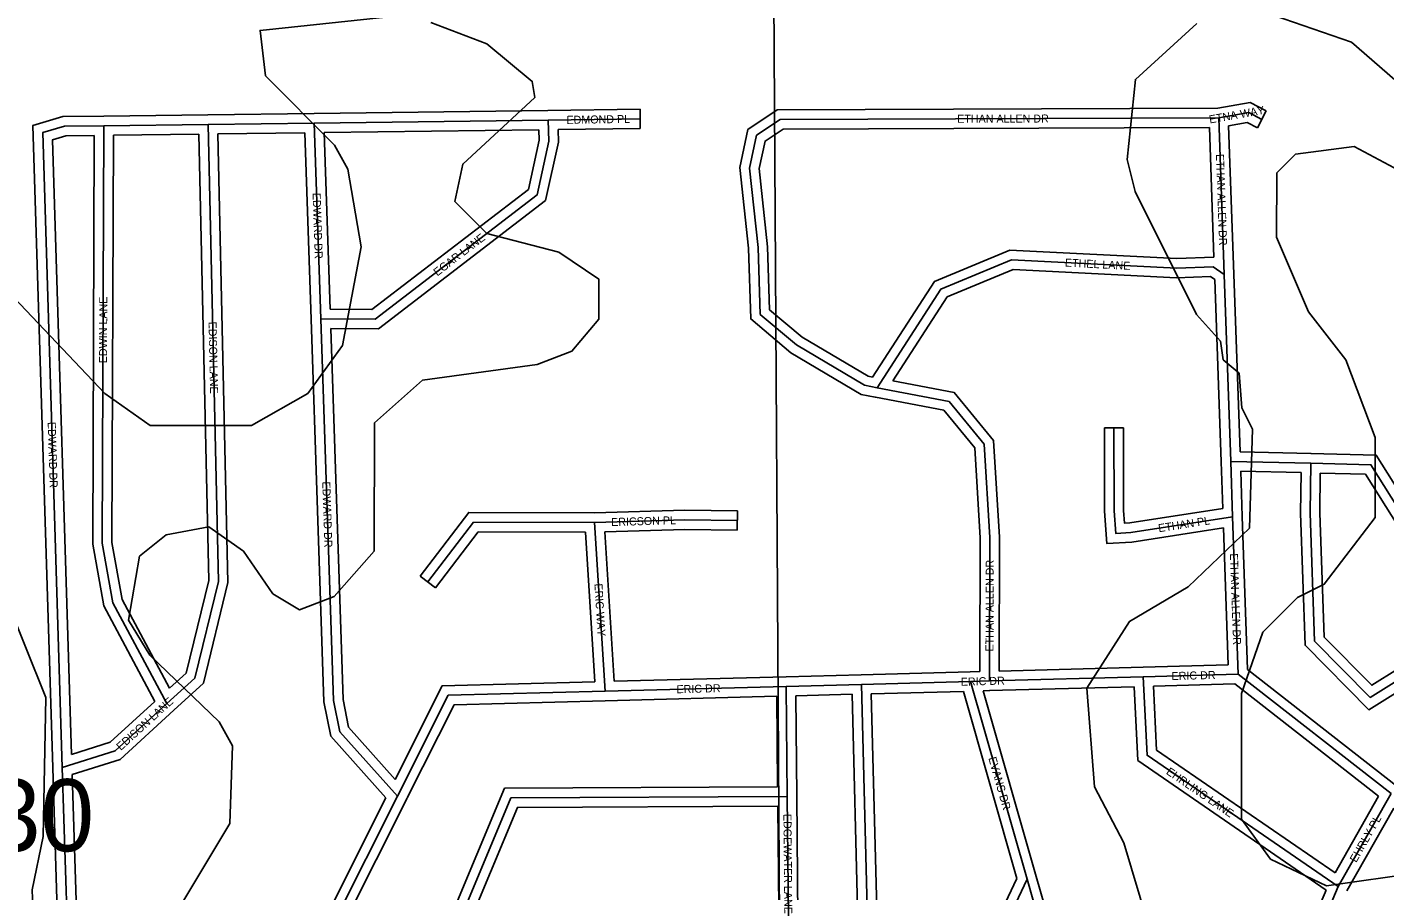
# Model space of a CAD drawing. Extents: x 457167 to 656239, y 1787309 to 1969297.
# Drawn here: x 577714 to 581955, y 1873995 to 1876691 of the extents above; entities that cross this region are included whole.
import ezdxf

# ---------------------------------------------------------------- set-up
doc = ezdxf.new("R2010")
doc.units = 0
for name, color, linetype in [('Level 1', 7, 'Continuous'), ('Level 2', 7, 'Continuous'), ('Level 31', 7, 'Continuous'), ('Level 32', 7, 'Continuous'), ('Level 34', 7, 'Continuous'), ('Level 7', 7, 'Continuous')]:
    doc.layers.add(name, color=color, linetype=linetype)

msp = doc.modelspace()

# ---------------------------------------------------------------- linework, layer by layer
at = {"layer": 'Level 1'}
msp.add_line((580044.647, 1877084.268), (580077.699, 1871707.169), dxfattribs=at)
at = {"layer": 'Level 31'}
for p, q in [((578279.362, 1876387.711), (577953.895, 1876383.669)), ((578610.875, 1876391.743), (578279.362, 1876387.711)), ((579341.346, 1876401.132), (578610.875, 1876391.743)), ((578610.875, 1876391.743), (578631.551, 1875781.157)), ((579628.955, 1876405.265), (579341.346, 1876401.132)), ((581436.002, 1876408.124), (581453.153, 1875919.365)), ((581453.153, 1875919.365), (581473.614, 1875335.691)), ((581473.614, 1875335.691), (581479.628, 1875162.589)), ((581473.614, 1875335.691), (581723.668, 1875329.733)), ((581722.084, 1875174.465), (581723.668, 1875329.733)), ((581479.628, 1875162.589), (581496.775, 1874670.921)), ((579519.327, 1874618.228), (579486.689, 1875144.474)), ((580660.933, 1874648.249), (580320.169, 1874639.126)), ((580719.795, 1874649.948), (580660.933, 1874648.249)), ((580660.933, 1874648.249), (580837.53, 1874030.803)), ((581200.555, 1874662.791), (580719.795, 1874649.948)), ((581496.775, 1874670.921), (581200.555, 1874662.791)), ((581496.775, 1874670.921), (581974.538, 1874298.328)), ((580085.357, 1874633.062), (579519.327, 1874618.228)), ((580320.169, 1874639.126), (580085.357, 1874633.062)), ((580085.357, 1874633.062), (580088.472, 1874289.786)), ((580320.169, 1874639.126), (580341.096, 1873824.907)), ((577824.003, 1874379.953), (577882.081, 1872499.116)), ((578870.615, 1874289.976), (578496.12, 1873546.181)), ((580088.472, 1874289.786), (580091.83, 1873909.781)), ((581974.538, 1874298.328), (581809.469, 1874008.115)), ((580837.53, 1874030.803), (580057.86, 1872392.042)), ((580837.53, 1874030.803), (580932.308, 1873699.341)), ((581809.469, 1874008.115), (581764.395, 1873902.388))]:
    msp.add_line(p, q, dxfattribs=at)
for points in [[(577953.895, 1876383.669), (577830.454, 1876382.111), (577762.965, 1876362.255), (577824.003, 1874379.953)], [(577953.895, 1876383.669), (577948.923, 1875080.05), (577982.256, 1874894.163), (578150.35, 1874579.171)], [(578279.362, 1876387.711), (578311.368, 1874960.742), (578237.876, 1874658.716), (578150.35, 1874579.171)], [(578631.551, 1875781.157), (578801.12, 1875779.349), (579306.822, 1876167.751), (579343.755, 1876335.309), (579341.346, 1876401.132)], [(581436.002, 1876408.124), (580066.077, 1876403.273), (579992.167, 1876353.971), (579970.641, 1876251.471), (579997.175, 1876003.781), (580003.746, 1875794.677), (580117.129, 1875699.173), (580330.03, 1875573.283), (580369.146, 1875565.566)], [(581436.002, 1876408.124), (581529.887, 1876424.662), (581570.885, 1876403.489)], [(580369.146, 1875565.566), (580567.98, 1875873.523), (580788.958, 1875965.072), (581304.937, 1875938.573), (581419.159, 1875943.069), (581453.153, 1875919.365)], [(578631.551, 1875781.157), (578671.06, 1874588.718), (578690.583, 1874491.587), (578870.615, 1874289.976)], [(580369.146, 1875565.566), (580593.673, 1875522.927), (580703.48, 1875389.25), (580721.023, 1875097.943), (580719.795, 1874649.948)], [(581479.628, 1875162.589), (581161.377, 1875113.413), (581114.286, 1875110.963), (581109.02, 1875181.519), (581108.906, 1875440.426)], [(581723.668, 1875329.733), (581911.367, 1875325.356), (582147.958, 1874948.886), (582179.237, 1874839.37), (582187.374, 1874771.718), (581909.596, 1874598.456), (581735.599, 1874774.076), (581722.084, 1875174.465)], [(579486.689, 1875144.474), (579768.27, 1875152.984), (579932.433, 1875151.191)], [(578965.489, 1874959.375), (579108.408, 1875145.986), (579486.689, 1875144.474)], [(581200.555, 1874662.791), (581212.47, 1874418.041), (581809.469, 1874008.115)], [(579519.327, 1874618.228), (579029.338, 1874605.426), (578870.615, 1874289.976)], [(578150.35, 1874579.171), (577988.92, 1874431.969), (577824.003, 1874379.953)], [(580088.472, 1874289.786), (579225.296, 1874285.021), (578788.511, 1873238.663)]]:
    msp.add_lwpolyline(points, dxfattribs=at)
at = {"layer": 'Level 32'}
for p, q in [((579340.961, 1876431.13), (578610.489, 1876421.741)), ((579628.524, 1876435.261), (579340.915, 1876431.129)), ((579629.386, 1876375.266), (579628.524, 1876435.261)), ((581584.651, 1876430.144), (581557.118, 1876376.833)), ((578278.99, 1876417.71), (577953.523, 1876413.667)), ((578610.51, 1876421.741), (578278.998, 1876417.71)), ((581466.9, 1876383.104), (581483.135, 1875920.416)), ((578250.036, 1876357.343), (577983.783, 1876354.036)), ((578581.885, 1876361.387), (578310.035, 1876358.081)), ((578581.885, 1876361.387), (578601.569, 1875780.141)), ((579312.439, 1876370.756), (578641.895, 1876362.138)), ((578641.895, 1876362.139), (578660.565, 1875810.85)), ((579629.386, 1876375.266), (579372.45, 1876371.575)), ((581407.041, 1876378.02), (581421.247, 1875973.176)), ((581483.135, 1875920.415), (581502.605, 1875365.008)), ((581423.698, 1875903.331), (581443.632, 1875334.64)), ((581078.906, 1875440.412), (581138.907, 1875440.44)), ((581502.605, 1875365.008), (581724.383, 1875359.725)), ((581443.631, 1875334.649), (581448.722, 1875188.169)), ((581504.701, 1875304.94), (581509.611, 1875163.63)), ((581504.701, 1875304.94), (581693.368, 1875300.446)), ((581692.079, 1875174.111), (581693.368, 1875300.446)), ((581752.091, 1875174.818), (581753.358, 1875299.031)), ((579932.76, 1875181.191), (579932.105, 1875121.193)), ((581509.611, 1875163.634), (581526.27, 1874685.963)), ((579487.46, 1874647.405), (579458.485, 1875114.586)), ((579547.479, 1874648.976), (579518.55, 1875115.422)), ((581450.824, 1875127.781), (581465.74, 1874700.08)), ((578941.67, 1874977.616), (578989.306, 1874941.134)), ((581199.754, 1874692.781), (580749.881, 1874680.762)), ((581465.74, 1874700.08), (581199.732, 1874692.781)), ((580084.572, 1874663.051), (579547.479, 1874648.976)), ((580319.395, 1874669.117), (580084.583, 1874663.052)), ((580660.13, 1874678.239), (580319.366, 1874669.116)), ((580689.875, 1874679.097), (580660.067, 1874678.237)), ((581526.27, 1874685.962), (581992.988, 1874321.985)), ((580055.635, 1874602.271), (579520.113, 1874588.237)), ((580055.635, 1874602.271), (580058.2, 1874319.618)), ((580290.95, 1874608.361), (580115.625, 1874603.831)), ((580115.625, 1874603.832), (580118.471, 1874290.057)), ((580290.95, 1874608.361), (580311.105, 1873824.136)), ((580638.486, 1874617.636), (580350.93, 1874609.938)), ((580350.93, 1874609.938), (580370.31, 1873855.923)), ((580638.485, 1874617.636), (580805.569, 1874033.453)), ((580720.661, 1874619.959), (580700.395, 1874619.374)), ((580700.395, 1874619.375), (580866.375, 1874039.053)), ((581172.019, 1874632.016), (580720.597, 1874619.957)), ((581486.825, 1874640.635), (581232.011, 1874633.642)), ((581486.825, 1874640.635), (581935.64, 1874290.619)), ((577794.018, 1874379.027), (577852.096, 1872498.19)), ((577854.691, 1874358.174), (577911.165, 1872529.265)), ((578834.635, 1874285.227), (578466.44, 1873553.941)), ((578901.508, 1874284.621), (578532.414, 1873551.55)), ((580118.471, 1874290.05), (580121.83, 1873910.046)), ((581935.64, 1874290.618), (581799.535, 1874051.327)), ((580058.737, 1874259.62), (580061.57, 1873939.104)), ((581983.447, 1874253.309), (581836.395, 1873994.772)), ((580805.569, 1874033.453), (580046.973, 1872438.987)), ((580866.375, 1874039.051), (580961.152, 1873707.587)), ((581772.24, 1873997.286), (581736.798, 1873914.153))]:
    msp.add_line(p, q, dxfattribs=at)
for points in [[(581433.328, 1876438.114), (580056.94, 1876433.241), (579965.325, 1876372.129), (579940.305, 1876252.993), (579967.225, 1876001.71), (579974.18, 1875780.356), (580099.71, 1875674.621), (580319.183, 1875544.845), (580363.34, 1875536.134)], [(581433.328, 1876438.114), (581534.656, 1876455.964), (581584.651, 1876430.144)], [(577953.516, 1876413.667), (577825.946, 1876412.058), (577732.265, 1876384.494), (577794.017, 1874379.03)], [(581466.9, 1876383.103), (581525.119, 1876393.36), (581557.118, 1876376.833)], [(577923.779, 1876353.285), (577834.96, 1876352.166), (577793.665, 1876340.015), (577852.77, 1874420.483)], [(577923.78, 1876353.285), (577918.913, 1875077.438), (577953.561, 1874884.211), (578112.903, 1874585.621)], [(577983.783, 1876354.037), (577978.934, 1875082.661), (578010.95, 1874904.114), (578158.68, 1874627.282)], [(578250.036, 1876357.344), (578281.286, 1874964.008), (578210.9, 1874674.738), (578158.68, 1874627.282)], [(578310.035, 1876358.081), (578341.449, 1874957.476), (578264.854, 1874642.695), (578172.625, 1874558.876)], [(578660.565, 1875810.849), (578791.07, 1875809.459), (579279.878, 1876184.884), (579313.635, 1876338.033), (579312.439, 1876370.756)], [(578662.575, 1875750.824), (578811.17, 1875749.24), (579333.766, 1876150.616), (579373.875, 1876332.585), (579372.449, 1876371.576)], [(581407.04, 1876378.02), (580075.213, 1876373.306), (580019.008, 1876335.814), (580000.976, 1876249.948), (580027.125, 1876005.853), (580033.311, 1875808.998), (580134.547, 1875723.726), (580340.878, 1875601.722), (580354.985, 1875598.939)], [(580354.985, 1875598.939), (580547.852, 1875897.657), (580783.733, 1875995.381), (581305.116, 1875968.603), (581421.247, 1875973.176)], [(580418.52, 1875586.726), (580588.108, 1875849.389), (580794.184, 1875934.763), (581304.757, 1875908.542), (581410.268, 1875912.696), (581423.697, 1875903.331)], [(578601.568, 1875780.164), (578641.157, 1874585.242), (578662.777, 1874477.684), (578834.635, 1874285.227)], [(578662.575, 1875750.824), (578700.961, 1874592.195), (578718.389, 1874505.49), (578863.631, 1874342.838)], [(580418.52, 1875586.726), (580609.953, 1875550.371), (580732.841, 1875400.77), (580751.026, 1875098.804), (580749.88, 1874680.763)], [(580363.55, 1875536.093), (580577.393, 1875495.482), (580674.119, 1875377.73), (580691.02, 1875097.082), (580689.875, 1874679.096)], [(581450.825, 1875127.781), (581164.455, 1875083.531), (581086.552, 1875079.479), (581079.02, 1875180.395), (581078.906, 1875440.412)], [(581448.722, 1875188.168), (581158.3, 1875143.294), (581142.02, 1875142.446), (581139.02, 1875182.643), (581138.907, 1875440.44)], [(581724.367, 1875359.726), (581928.188, 1875354.973), (582175.631, 1874961.232), (582208.738, 1874845.318), (582219.438, 1874756.36), (581905.147, 1874560.321), (581706.011, 1874761.314), (581692.08, 1875174.111)], [(581753.358, 1875299.031), (581894.546, 1875295.741), (582120.285, 1874936.541), (582149.735, 1874833.422), (582155.31, 1874787.076), (581914.046, 1874636.59), (581765.185, 1874786.84), (581752.09, 1875174.818)], [(578941.67, 1874977.616), (579093.642, 1875176.045), (579486.296, 1875174.476)], [(579486.295, 1875174.476), (579767.98, 1875182.99), (579932.76, 1875181.191)], [(578989.306, 1874941.134), (579123.175, 1875115.926), (579458.485, 1875114.586)], [(579518.55, 1875115.422), (579768.56, 1875122.979), (579932.105, 1875121.193)], [(579487.46, 1874647.405), (579010.608, 1874634.946), (578863.631, 1874342.838)], [(581172.019, 1874632.016), (581183.228, 1874401.728), (581772.24, 1873997.286)], [(581232.011, 1874633.642), (581241.712, 1874434.354), (581799.535, 1874051.328)], [(578112.903, 1874585.621), (577973.59, 1874458.592), (577852.77, 1874420.482)], [(579520.11, 1874588.237), (579048.069, 1874575.904), (578901.51, 1874284.629)], [(578172.625, 1874558.876), (578004.248, 1874405.346), (577854.691, 1874358.174)], [(580058.2, 1874319.618), (579205.264, 1874314.911), (578778.55, 1873292.678)], [(580058.737, 1874259.62), (579245.329, 1874255.131), (578823.736, 1873245.166)]]:
    msp.add_lwpolyline(points, dxfattribs=at)
at = {"layer": 'Level 7'}
for points in [[(578833.455, 1876722.581), (578441.62, 1876681.287), (578458.132, 1876539.576), (578674.647, 1876322.603), (578716.258, 1876247.512), (578757.68, 1876005.719), (578699.003, 1875697.344), (578590.462, 1875547.421), (578415.31, 1875447.549), (578098.526, 1875447.877), (577956.913, 1875548.078), (577615.515, 1875906.891)], [(581609.465, 1876727.975), (581851.12, 1876644.355), (582034.363, 1876485.763)], [(578196.97, 1873955.586), (578347.28, 1874205.51), (578355.879, 1874447.264), (578314.297, 1874522.325), (578097.782, 1874730.956), (578031.19, 1874839.428), (578064.76, 1875039.461), (578148.19, 1875106.062), (578281.601, 1875130.934), (578389.874, 1875055.783), (578481.446, 1874922.301), (578564.738, 1874872.181), (578673.179, 1874913.772), (578798.35, 1875055.355), (578798.776, 1875455.491), (578948.957, 1875588.714), (579307.481, 1875638.336), (579415.883, 1875679.917), (579499.383, 1875779.86), (579499.512, 1875904.901), (579374.53, 1875988.402), (579149.516, 1876046.981), (579049.614, 1876147.143), (579074.723, 1876263.825), (579300.025, 1876471.999), (579291.754, 1876522.02), (579150.17, 1876638.861), (578975.168, 1876705.741)], [(581214.664, 1873894.03), (581139.9, 1874144.213), (581048.368, 1874319.376), (581023.685, 1874627.82), (581157.295, 1874836.094), (581340.816, 1874944.266), (581532.748, 1875127.47), (581541.415, 1875435.915), (581508.134, 1875502.636), (581499.893, 1875611.007), (581449.942, 1875652.757), (581441.671, 1875711.108), (581366.71, 1875794.539), (581175.394, 1876178.234), (581150.482, 1876278.276), (581175.75, 1876528.359), (581367.682, 1876703.193)], [(581984.085, 1876252.379), (581859.102, 1876319.2), (581675.7, 1876294.388), (581617.28, 1876236.097), (581617.061, 1876036.034), (581716.865, 1875802.521), (581833.407, 1875652.33), (581924.85, 1875410.486), (581924.583, 1875160.392), (581765.972, 1874952.149), (581682.571, 1874910.567), (581574.071, 1874802.326), (581507.191, 1874610.652), (581506.765, 1874218.846), (581598.337, 1874093.705), (581773.3, 1874010.155), (582065.135, 1874051.536)], [(577581.292, 1875073.299), (577772.499, 1874597.933), (577763.713, 1874164.446), (577730.204, 1873997.754), (577738.305, 1873781.011), (577829.779, 1873572.508), (578287.849, 1873188.545), (578454.353, 1872971.642), (578495.905, 1872838.201), (578495.607, 1872546.426), (578403.519, 1872196.401), (578419.733, 1871754.574), (578453.054, 1871737.874)]]:
    msp.add_lwpolyline(points, dxfattribs=at)

# ---------------------------------------------------------------- texts
at = {"layer": 'Level 2'}
msp.add_text('02-12-30', height=225, dxfattribs=at).set_placement((576718.835, 1874118.414))
at = {"layer": 'Level 34'}
for s, height, rotation, p in [('ETNA WAY', 25, 9.990019, (581408.343, 1876390.559)), ('EDMOND PL', 25, 0.822897, (579398.883, 1876389.458)), ('ETHAN ALLEN DR', 24.99916, 0.202556, (580619.28, 1876392.733)), ('ETHAN ALLEN DR', 25, 272.009242, (581427.465, 1876295.036)), ('EDWARD DR', 25, 271.939058, (578605.747, 1876173.851)), ('EGAR LANE', 25, 37.525397, (578995.266, 1875912.7)), ('ETHEL LANE', 25, 357.059686, (580955.245, 1875944.016)), ('EDWIN LANE', 25, 89.780972, (577963.565, 1875642.048)), ('EDISON LANE', 25, 271.284342, (578280.676, 1875771.717)), ('EDWARD DR', 25, 271.763178, (577778.286, 1875458.551)), ('EDWARD DR', 25, 271.897125, (578635.903, 1875272.35)), ('ERICSON PL', 25, 1.730714, (579538.605, 1875133.538)), ('ETHAN PL', 25, 8.783472, (581249.108, 1875114.321)), ('ETHAN ALLEN DR', 25, 89.842458, (580732.546, 1874742.101)), ('ETHAN ALLEN DR', 25, 271.996836, (581471.116, 1875048.051)), ('ERIC WAY', 25, 273.548508, (579486, 1874953.666)), ('ERIC DR', 25, 1.652425, (580630.749, 1874634.874)), ('ERIC DR', 25, 1.571775, (581289.03, 1874652.715)), ('ERIC DR', 25, 1.500956, (579742.69, 1874611.578)), ('EDISON LANE', 25, 42.358953, (578006.84, 1874431.396)), ('EVANS DR', 25, 285.960736, (580716.297, 1874409.22)), ('EHRLING LANE', 25, 325.524414, (581269.714, 1874361.368)), ('EDGEWATER LANE', 25, 270.505797, (580076.459, 1874234.786)), ('EHRLY PL', 25, 60.368925, (581865.495, 1874081.336))]:
    msp.add_text(s, height=height, rotation=rotation, dxfattribs=at).set_placement(p)

doc.saveas('drawing.dxf')
